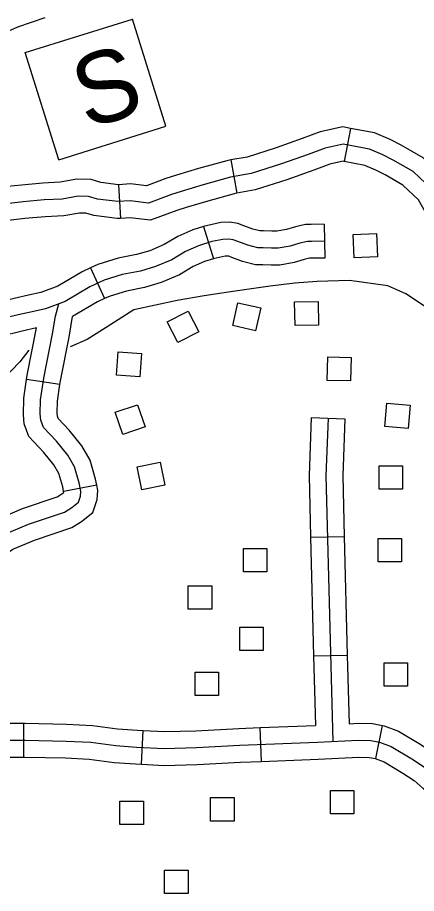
# Model space of a CAD drawing. Extents: x 1370130 to 1380143, y 377636 to 380256.
# Drawn here: x 1377637.6 to 1377687.4, y 378847.7 to 378956.8 of the extents above; entities that cross this region are included whole.
import ezdxf

# ---------------------------------------------------------------- set-up
doc = ezdxf.new("R2010")
doc.units = 0
for name, color, linetype in [('Level 31', 7, 'Continuous'), ('Level 32', 7, 'Continuous'), ('Level 35', 7, 'Continuous'), ('Level 56', 7, 'Continuous'), ('Level 57', 7, 'Continuous')]:
    doc.layers.add(name, color=color, linetype=linetype)

msp = doc.modelspace()

# ---------------------------------------------------------------- linework, layer by layer
at = {"layer": 'Level 31'}
msp.add_lwpolyline([(1377627.78, 378951.16), (1377628.63, 378951.6), (1377637.69, 378955.6), (1377641.1, 378956.77)], dxfattribs=at)
at = {"layer": 'Level 32'}
for p, q in [((1377679.17, 378942.97), (1377678.36, 378938.85)), ((1377664.24, 378939.03), (1377664.99, 378934.89)), ((1377650.23, 378935.95), (1377650.48, 378931.76)), ((1377660.82, 378930.73), (1377662.06, 378926.71)), ((1377675.87, 378931.02), (1377675.94, 378926.82)), ((1377646.76, 378925.6), (1377648.5, 378921.77)), ((1377642.93, 378911.06), (1377638.78, 378911.7)), ((1377674.27, 378906.96), (1377678.46, 378906.8)), ((1377647.52, 378898.54), (1377643.4, 378897.74)), ((1377674.18, 378892.05), (1377678.38, 378892.16)), ((1377674.55, 378877.27), (1377678.75, 378877.38)), ((1377638.45, 378864.68), (1377638.45, 378868.88)), ((1377668.05, 378864.14), (1377667.88, 378868.34)), ((1377682.32, 378864.48), (1377683.12, 378868.6)), ((1377653.09, 378863.79), (1377653.3, 378867.98))]:
    msp.add_line(p, q, dxfattribs=at)
for points in [[(1377679.17, 378942.97), (1377678.2, 378943.16), (1377675.37, 378942.54), (1377673.13, 378941.69), (1377669.89, 378940.53), (1377666.28, 378939.4), (1377664.24, 378939.03)], [(1377692.44, 378934.05), (1377692.22, 378934.47), (1377690.99, 378936.65), (1377688.22, 378939.29), (1377685.48, 378940.86), (1377684.09, 378941.56), (1377682.16, 378942.39), (1377679.17, 378942.97)], [(1377689.31, 378935.35), (1377686.96, 378937.59), (1377684.48, 378939.01), (1377683.2, 378939.66), (1377681.54, 378940.37), (1377678.23, 378941.01), (1377675.98, 378940.52), (1377673.86, 378939.72), (1377670.56, 378938.54), (1377666.79, 378937.36), (1377664.19, 378936.88), (1377660.77, 378935.94), (1377658.06, 378935.11), (1377656.83, 378934.74), (1377653.97, 378933.66), (1377651.69, 378933.93), (1377650.15, 378933.84), (1377647.62, 378934.17), (1377646.5, 378934.5), (1377645.2, 378934.52), (1377643.2, 378934.17), (1377640.96, 378934.05), (1377638.36, 378933.82), (1377636.63, 378933.63)], [(1377664.24, 378939.03), (1377663.72, 378938.93), (1377660.19, 378937.96), (1377657.45, 378937.12), (1377656.15, 378936.73), (1377653.71, 378935.81), (1377651.75, 378936.04), (1377650.23, 378935.95)], [(1377678.36, 378938.85), (1377678.25, 378938.87), (1377676.58, 378938.51), (1377674.59, 378937.75), (1377671.23, 378936.54), (1377667.29, 378935.31), (1377664.99, 378934.89)], [(1377688.73, 378932.09), (1377688.53, 378932.46), (1377687.64, 378934.05), (1377685.69, 378935.9), (1377683.48, 378937.16), (1377682.31, 378937.76), (1377680.92, 378938.35), (1377678.36, 378938.85)], [(1377650.23, 378935.95), (1377650.22, 378935.95), (1377648.05, 378936.23), (1377646.82, 378936.6), (1377645.04, 378936.63), (1377642.96, 378936.26), (1377640.81, 378936.15), (1377638.16, 378935.91), (1377636.42, 378935.72), (1377635.43, 378935.62), (1377635.18, 378935.56)], [(1377664.99, 378934.89), (1377664.66, 378934.83), (1377661.36, 378933.92), (1377658.67, 378933.1), (1377657.5, 378932.75), (1377654.23, 378931.52), (1377651.63, 378931.83), (1377650.48, 378931.76)], [(1377650.48, 378931.76), (1377650.07, 378931.73), (1377647.18, 378932.11), (1377646.18, 378932.41), (1377645.37, 378932.42), (1377643.44, 378932.08), (1377641.11, 378931.96), (1377638.57, 378931.73), (1377636.85, 378931.54), (1377636.17, 378931.47), (1377636.23, 378931.49)], [(1377660.82, 378930.73), (1377659.49, 378930.32), (1377657.62, 378929.51), (1377655.93, 378928.49), (1377654.13, 378927.73), (1377652.48, 378927.24), (1377650.19, 378926.79), (1377647.68, 378926.01), (1377646.76, 378925.6)], [(1377675.87, 378931.02), (1377674.26, 378930.99), (1377673.56, 378930.99), (1377672.3, 378930.69), (1377671.18, 378930.36), (1377669.97, 378930.15), (1377669.35, 378930.15), (1377668.29, 378930.19), (1377667.85, 378930.19), (1377666.96, 378930.41), (1377665.86, 378930.82), (1377665.1, 378931.12), (1377664.09, 378931.28), (1377663, 378931.23), (1377661.36, 378930.89), (1377660.82, 378930.73)], [(1377675.9, 378928.92), (1377674.28, 378928.89), (1377673.8, 378928.89), (1377672.84, 378928.66), (1377671.65, 378928.31), (1377670.15, 378928.05), (1377669.32, 378928.05), (1377668.26, 378928.09), (1377667.59, 378928.09), (1377666.34, 378928.41), (1377665.12, 378928.86), (1377664.54, 378929.08), (1377663.97, 378929.18), (1377663.26, 378929.14), (1377661.88, 378928.86), (1377660.22, 378928.34), (1377658.58, 378927.64), (1377656.88, 378926.61), (1377654.83, 378925.75), (1377652.98, 378925.2), (1377650.7, 378924.75), (1377648.43, 378924.05), (1377646.66, 378923.25), (1377643.59, 378921.42), (1377641.15, 378920.49), (1377639.46, 378920.14), (1377637.73, 378919.75), (1377635.13, 378919.11)], [(1377662.06, 378926.71), (1377660.94, 378926.37), (1377659.55, 378925.77), (1377657.84, 378924.74), (1377655.54, 378923.76), (1377653.48, 378923.16), (1377651.22, 378922.71), (1377649.18, 378922.08), (1377648.5, 378921.77)], [(1377675.94, 378926.82), (1377674.3, 378926.79), (1377674.04, 378926.79), (1377673.38, 378926.63), (1377672.13, 378926.26), (1377670.33, 378925.95), (1377669.28, 378925.95), (1377668.23, 378925.99), (1377667.32, 378925.99), (1377665.71, 378926.4), (1377664.37, 378926.89), (1377663.98, 378927.04), (1377663.84, 378927.07), (1377663.53, 378927.05), (1377662.41, 378926.82), (1377662.06, 378926.71)], [(1377646.76, 378925.6), (1377645.69, 378925.11), (1377642.67, 378923.32), (1377640.56, 378922.51), (1377639.01, 378922.19), (1377637.25, 378921.8), (1377634.73, 378921.17), (1377633.48, 378920.99)], [(1377648.5, 378921.77), (1377647.64, 378921.38), (1377644.51, 378919.52)], [(1377636.08, 378892.42), (1377639.03, 378893.67), (1377643.51, 378895.16), (1377644.42, 378895.74), (1377645.25, 378896.4), (1377645.5, 378897.15), (1377645.54, 378897.73), (1377645.33, 378898.81), (1377644.75, 378900.8), (1377643.92, 378902.26), (1377642.51, 378904), (1377640.89, 378905.7), (1377640.56, 378906.65), (1377640.48, 378907.4), (1377640.52, 378909.18), (1377640.93, 378911.88), (1377642.01, 378917.36), (1377642.39, 378919.56), (1377642.78, 378921.11)], [(1377642.93, 378911.06), (1377643, 378911.52), (1377644.08, 378916.98), (1377644.51, 378919.52)], [(1377640.02, 378918.11), (1377638.21, 378917.71), (1377635.54, 378917.05), (1377634.09, 378916.83)], [(1377638.78, 378911.7), (1377638.87, 378912.24), (1377640.02, 378918.11)], [(1377643.4, 378897.74), (1377643.29, 378898.32), (1377642.8, 378899.98), (1377642.18, 378901.07), (1377640.93, 378902.61), (1377639.06, 378904.58), (1377638.5, 378906.19), (1377638.38, 378907.31), (1377638.42, 378909.37), (1377638.78, 378911.7)], [(1377647.52, 378898.54), (1377647.37, 378899.3), (1377646.7, 378901.63), (1377645.66, 378903.44), (1377644.09, 378905.38), (1377642.73, 378906.82), (1377642.62, 378907.12), (1377642.58, 378907.49), (1377642.62, 378909), (1377642.93, 378911.06)], [(1377674.27, 378906.96), (1377673.98, 378899.73), (1377674.18, 378892.05)], [(1377676.37, 378906.88), (1377676.08, 378899.71), (1377676.93, 378866.62)], [(1377678.46, 378906.8), (1377678.18, 378899.7), (1377678.38, 378892.16)], [(1377632.23, 378892.15), (1377632.91, 378892.85), (1377635.09, 378894.28), (1377638.29, 378895.63), (1377642.6, 378897.07), (1377643.19, 378897.45), (1377643.42, 378897.63), (1377643.4, 378897.74)], [(1377635.24, 378889.22), (1377635.6, 378889.59), (1377637.08, 378890.56), (1377639.77, 378891.7), (1377644.42, 378893.25), (1377645.64, 378894.03), (1377647.04, 378895.15), (1377647.57, 378896.74), (1377647.65, 378897.86), (1377647.52, 378898.54)], [(1377674.18, 378892.05), (1377674.55, 378877.27)], [(1377678.38, 378892.16), (1377678.75, 378877.38)], [(1377674.55, 378877.27), (1377674.78, 378868.62)], [(1377678.75, 378877.38), (1377678.97, 378868.82)], [(1377623.41, 378867.67), (1377625.15, 378868.01), (1377627.02, 378868.12), (1377630.32, 378868.47), (1377632.37, 378868.8), (1377634.21, 378868.88), (1377638.45, 378868.88)], [(1377638.45, 378868.88), (1377638.61, 378868.88), (1377643.77, 378868.77), (1377646.98, 378868.62), (1377650.12, 378868.19), (1377652.59, 378868.02), (1377653.3, 378867.98)], [(1377653.3, 378867.98), (1377655.97, 378867.85), (1377659.87, 378867.95), (1377665.25, 378868.23), (1377667.88, 378868.34)], [(1377667.88, 378868.34), (1377674.78, 378868.62)], [(1377678.97, 378868.82), (1377680.13, 378868.88), (1377681.91, 378868.84), (1377683.12, 378868.6)], [(1377683.12, 378868.6), (1377683.35, 378868.56), (1377685.15, 378867.9), (1377687.91, 378866.25), (1377689.64, 378865.1), (1377691.2, 378863.71), (1377693.28, 378861.36), (1377695.48, 378858.44)], [(1377634.25, 378866.78), (1377638.59, 378866.78), (1377643.7, 378866.67), (1377646.79, 378866.53), (1377649.91, 378866.1), (1377652.47, 378865.92), (1377655.94, 378865.75), (1377659.96, 378865.85), (1377665.35, 378866.14), (1377675.04, 378866.53), (1377680.16, 378866.78), (1377681.68, 378866.74), (1377682.78, 378866.53), (1377684.24, 378865.99), (1377686.79, 378864.47), (1377688.36, 378863.44)], [(1377624.33, 378863.53), (1377624.8, 378863.67), (1377625.68, 378863.84), (1377627.36, 378863.94), (1377630.87, 378864.3), (1377632.8, 378864.61), (1377634.3, 378864.68), (1377638.45, 378864.68)], [(1377638.45, 378864.68), (1377638.56, 378864.68), (1377643.63, 378864.57), (1377646.59, 378864.43), (1377649.69, 378864.01), (1377652.34, 378863.83), (1377653.09, 378863.79)], [(1377653.09, 378863.79), (1377655.92, 378863.64), (1377660.04, 378863.75), (1377665.45, 378864.04), (1377668.05, 378864.14)], [(1377668.05, 378864.14), (1377675.14, 378864.43), (1377680.18, 378864.67), (1377681.46, 378864.64), (1377682.32, 378864.48)], [(1377682.22, 378864.5), (1377683.33, 378864.09), (1377685.68, 378862.69), (1377687.07, 378861.77), (1377688.21, 378860.75), (1377690.03, 378858.7), (1377692.12, 378855.91)]]:
    msp.add_lwpolyline(points, dxfattribs=at)
at = {"layer": 'Level 35'}
for points in [[(1377714.47, 378909.08), (1377713.16, 378909.48), (1377705.93, 378913.01), (1377701.46, 378914.69), (1377693.05, 378918.15), (1377690.37, 378919.51), (1377686.04, 378922.36), (1377683.82, 378923.34), (1377679.02, 378924.02), (1377675.01, 378923.9), (1377672.23, 378923.7), (1377669.12, 378923.32), (1377664.48, 378922.67), (1377660.92, 378922.12), (1377657.56, 378921.54), (1377652.13, 378920.36), (1377648.25, 378917.89), (1377646.35, 378916.68), (1377644.23, 378915.76)], [(1377639.06, 378915.36), (1377637.96, 378913.9), (1377634.73, 378910.63), (1377632.6, 378909.27), (1377629.29, 378907.63), (1377628.18, 378906.68), (1377625.77, 378903.96), (1377623.51, 378900.55), (1377622.18, 378899.26), (1377620.07, 378898.34), (1377617.44, 378897.67), (1377615.6, 378896.93), (1377614.21, 378896.11), (1377611.87, 378894.07), (1377609.86, 378892.07), (1377607.96, 378889.92), (1377605.89, 378887.91), (1377603.93, 378886.55), (1377602.48, 378886.07), (1377599.26, 378885.42), (1377597.48, 378884.71), (1377596.36, 378884.49), (1377594.61, 378884.56)]]:
    msp.add_lwpolyline(points, dxfattribs=at)
at = {"layer": 'Level 56'}
for points in [[(1377682.4, 378929.87), (1377682.53, 378926.96), (1377679.61, 378926.83), (1377679.48, 378929.74)], [(1377667.32, 378917.75), (1377664.48, 378918.4), (1377665.13, 378921.25), (1377667.97, 378920.6)], [(1377672.24, 378918.43), (1377672.19, 378921.35), (1377675.11, 378921.4), (1377675.16, 378918.48)], [(1377657.64, 378916.29), (1377656.32, 378918.89), (1377658.93, 378920.21), (1377660.25, 378917.61)], [(1377649.99, 378912.23), (1377650.2, 378915.14), (1377653.11, 378914.92), (1377652.9, 378912.02)], [(1377676.24, 378911.59), (1377676.31, 378914.51), (1377679.23, 378914.44), (1377679.17, 378911.53)], [(1377683.41, 378905.84), (1377683.66, 378908.74), (1377686.57, 378908.49), (1377686.32, 378905.58)], [(1377650.78, 378904.85), (1377649.84, 378907.61), (1377652.6, 378908.55), (1377653.55, 378905.8)], [(1377653.14, 378897.97), (1377652.58, 378900.83), (1377655.44, 378901.4), (1377656.01, 378898.54)], [(1377682.72, 378898.03), (1377682.72, 378900.94), (1377685.64, 378900.94), (1377685.64, 378898.03)], [(1377682.59, 378888.98), (1377682.59, 378891.9), (1377685.51, 378891.9), (1377685.51, 378888.98)], [(1377665.81, 378887.73), (1377665.81, 378890.65), (1377668.73, 378890.65), (1377668.73, 378887.73)], [(1377658.93, 378883.08), (1377658.93, 378885.99), (1377661.86, 378885.99), (1377661.86, 378883.08)], [(1377665.36, 378877.95), (1377665.36, 378880.86), (1377668.28, 378880.86), (1377668.28, 378877.95)], [(1377683.34, 378873.51), (1377683.34, 378876.43), (1377686.26, 378876.43), (1377686.26, 378873.51)], [(1377659.79, 378872.35), (1377659.79, 378875.26), (1377662.72, 378875.26), (1377662.72, 378872.35)], [(1377661.72, 378856.71), (1377661.72, 378859.63), (1377664.65, 378859.63), (1377664.65, 378856.71)], [(1377676.65, 378857.61), (1377676.65, 378860.52), (1377679.57, 378860.52), (1377679.57, 378857.61)], [(1377650.42, 378856.29), (1377650.42, 378859.2), (1377653.35, 378859.2), (1377653.35, 378856.29)], [(1377655.98, 378847.69), (1377655.98, 378850.61), (1377658.91, 378850.61), (1377658.91, 378847.69)]]:
    msp.add_lwpolyline(points, close=True, dxfattribs=at)
at = {"layer": 'Level 57'}
for p, q in [((1377638.62, 378952.41), (1377651.98, 378956.58)), ((1377656.15, 378943.22), (1377651.98, 378956.58)), ((1377642.79, 378939.05), (1377638.62, 378952.41)), ((1377642.79, 378939.05), (1377656.15, 378943.22))]:
    msp.add_line(p, q, dxfattribs=at)

# ---------------------------------------------------------------- texts
msp.add_text('S', height=8.87, rotation=17.3405, dxfattribs=at).set_placement((1377646.25, 378942.81))

doc.saveas('drawing.dxf')
